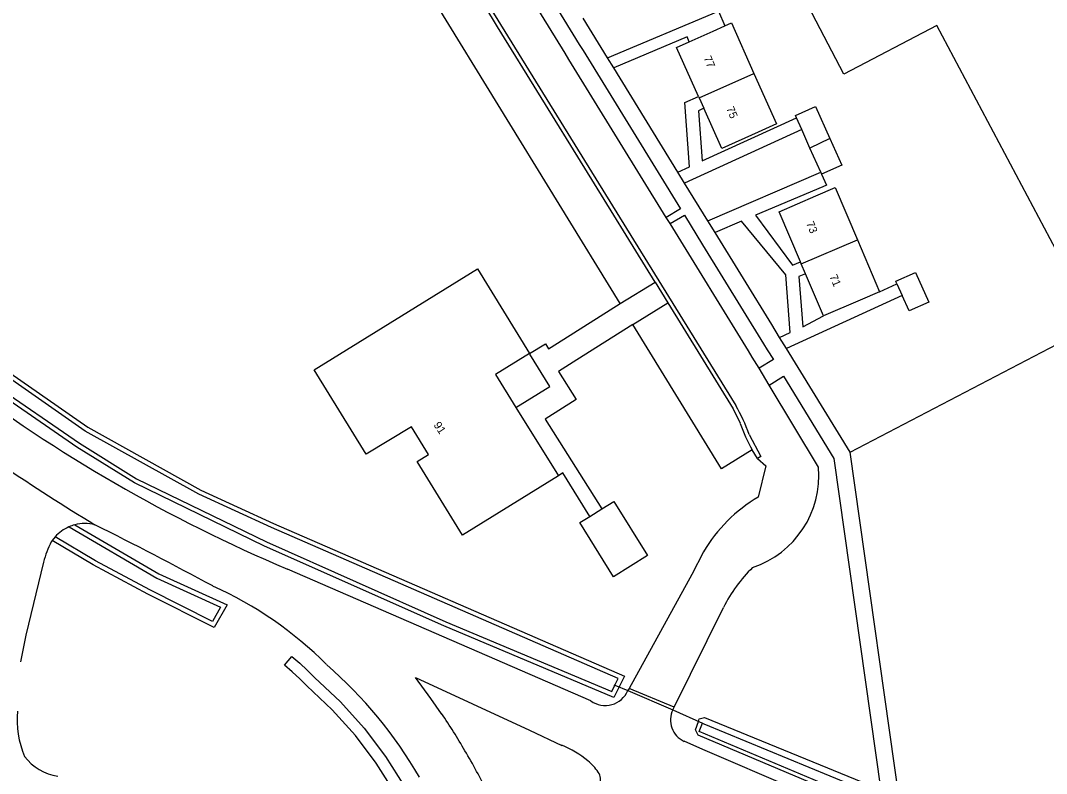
# Model space of a CAD drawing. Extents: x 158132 to 159658, y 385257 to 387209.
# Drawn here: x 158545 to 158673.1, y 386868.4 to 386962.3 of the extents above; entities that cross this region are included whole.
import ezdxf

# ---------------------------------------------------------------- set-up
doc = ezdxf.new("R2010")
doc.units = 0
for name, color, linetype in [('IMGEO_Duiker', 7, 'Continuous'), ('IMGEO_Gemengd_bos', 7, 'Continuous'), ('IMGEO_Groenvoorziening', 7, 'Continuous'), ('IMGEO_Pand', 7, 'Continuous'), ('IMGEO_Pand_nummerreeks', 7, 'Continuous'), ('IMGEO_Pand_overbouw', 7, 'Continuous'), ('IMGEO_Parkeervlak_open', 7, 'Continuous'), ('IMGEO_Rijbaan_lokaal_gesloten', 7, 'Continuous'), ('IMGEO_Rijbaan_lokaal_open', 7, 'Continuous'), ('IMGEO_Voetpad_gesloten', 7, 'Continuous'), ('IMGEO_Voetpad_open', 7, 'Continuous'), ('IMGEO_Waterloop', 7, 'Continuous')]:
    doc.layers.add(name, color=color, linetype=linetype)

msp = doc.modelspace()

# ---------------------------------------------------------------- linework, layer by layer
at = {"layer": 'IMGEO_Duiker'}
msp.add_lwpolyline([(158619.11, 386879.44), (158619.24, 386879.39), (158620.83, 386878.7), (158626.46, 386876.3), (158630.15, 386874.64), (158630.33, 386874.56)], dxfattribs=at)
at = {"layer": 'IMGEO_Gemengd_bos'}
msp.add_lwpolyline([(158648.61, 386908.46), (158679.26, 386924.45), (158659.44, 386961.72), (158647.81, 386955.65), (158601.87, 387043.7)], dxfattribs=at)
at = {"layer": 'IMGEO_Groenvoorziening'}
for points in [[(158541.3, 386919.97), (158553.38, 386911.58), (158567.53, 386903.71), (158576.57, 386899.58), (158620.42, 386880.49), (158619.77, 386879.16), (158619.11, 386877.83), (158597.88, 386886.78), (158575.48, 386896.74), (158559.21, 386904.65), (158552.04, 386909.09), (158541.19, 386916.52)], [(158551.76, 386899.4), (158562.26, 386893.26), (158570.79, 386889.39), (158569.19, 386886.59), (158560.89, 386890.75), (158554.07, 386894.41), (158548.96, 386897.43)], [(158651.05, 386866.89), (158651.9, 386866.34), (158651.69, 386865.11), (158651.3, 386864.28), (158650.59, 386864.28), (158629.61, 386873.15), (158629.28, 386873.81), (158629.65, 386874.86), (158629.77, 386875.18), (158630.42, 386875.36), (158651.05, 386866.89)]]:
    msp.add_lwpolyline(points, dxfattribs=at)
at = {"layer": 'IMGEO_Pand'}
for points in [[(158628.51, 386959.69), (158631.48, 386961.02), (158632.96, 386961.69)], [(158632.96, 386961.69), (158633.78, 386962.05), (158636.6, 386955.75)], [(158629.66, 386952.87), (158626.92, 386958.98), (158628.51, 386959.69)], [(158629.74, 386952.68), (158636.6, 386955.75)], [(158636.6, 386955.75), (158639.43, 386949.45), (158637.13, 386948.42), (158632.57, 386946.38), (158630.32, 386951.39)], [(158629.66, 386952.87), (158629.74, 386952.68)], [(158629.74, 386952.68), (158630.32, 386951.39)], [(158641.9, 386950.19), (158641.77, 386950.48), (158644.28, 386951.61), (158646.08, 386947.6)], [(158642.56, 386948.72), (158641.9, 386950.19)], [(158643.58, 386946.43), (158642.56, 386948.72)], [(158646.08, 386947.6), (158643.58, 386946.43)], [(158646.08, 386947.6), (158647.57, 386944.29), (158645.05, 386943.16)], [(158644.93, 386943.42), (158643.58, 386946.43)], [(158644.93, 386943.42), (158645.05, 386943.16)], [(158642.39, 386932.24), (158639.73, 386938.48), (158644.33, 386940.45), (158646.74, 386941.48), (158649.51, 386934.98)], [(158642.5, 386931.99), (158649.51, 386934.98)], [(158649.51, 386934.98), (158652.28, 386928.48)], [(158642.5, 386931.99), (158642.39, 386932.24)], [(158643.03, 386930.74), (158642.5, 386931.99)], [(158612.17, 386905.52), (158600.21, 386898.12), (158594.54, 386907.31), (158595.94, 386908.17), (158593.81, 386911.62), (158588.18, 386908.2), (158581.66, 386918.75), (158602.06, 386931.34), (158608.58, 386920.77)], [(158645.27, 386925.49), (158643.03, 386930.74)], [(158654.46, 386929.47), (158654.32, 386929.79), (158656.77, 386930.89), (158658.43, 386927.19), (158655.98, 386926.09), (158655.12, 386928.01)], [(158654.46, 386929.47), (158655.12, 386928.01)], [(158652.28, 386928.48), (158649.87, 386927.45), (158645.27, 386925.49)], [(158608.58, 386920.77), (158604.31, 386918.14), (158606.86, 386914.04), (158612.17, 386905.52)], [(158617.6, 386901.39), (158619.1, 386902.32), (158623.29, 386895.56), (158619.04, 386892.92), (158614.85, 386899.68), (158616.09, 386900.45)], [(158616.09, 386900.45), (158617.6, 386901.39)]]:
    msp.add_lwpolyline(points, dxfattribs=at)
at = {"layer": 'IMGEO_Pand_overbouw'}
msp.add_lwpolyline([(158608.62, 386920.71), (158608.58, 386920.77), (158604.31, 386918.14), (158606.86, 386914.04), (158611.12, 386916.66)], close=True, dxfattribs=at)
at = {"layer": 'IMGEO_Parkeervlak_open'}
for points in [[(158619.87, 386927), (158597.01, 386964.2)], [(158636.39, 386908.74), (158632.55, 386906.39), (158621.45, 386924.4)]]:
    msp.add_lwpolyline(points, dxfattribs=at)
at = {"layer": 'IMGEO_Rijbaan_lokaal_gesloten'}
for points in [[(158548.96, 386897.43), (158548.84, 386897.27)], [(158549.31, 386897.89), (158548.96, 386897.43)], [(158547.87, 386894.73), (158545.66, 386885.64), (158544.99, 386882.31)], [(158616.23, 386877.41), (158578.35, 386893.85)], [(158597.59, 386875.82), (158596.25, 386877.72), (158594.32, 386880.32), (158601.45, 386877.03), (158608.58, 386873.75)], [(158620.99, 386878.98), (158620.83, 386878.7)], [(158626.63, 386876.64), (158620.99, 386878.98)], [(158626.46, 386876.3), (158626.63, 386876.64)], [(158608.58, 386873.75), (158612.61, 386871.86)], [(158653.1, 386861.53), (158630.22, 386871.36), (158627.88, 386872.37)]]:
    msp.add_lwpolyline(points, dxfattribs=at)
for centre, radius, start, end in [((158654.05, 387072.79), 194.29, 232.8648, 247.0704), ((158685.5, 387116.71), 253.85, 235.797, 238.8745), ((158553.03, 386894.54), 5.02, 75.5928, 104.6347), ((158553.05, 386894.56), 5.01, 113.585, 138.3403), ((158553.02, 386894.56), 5, 104.6401, 113.2873), ((158290.06, 386372.24), 589.68, 61.7656, 63.37979), ((158558.82, 386892), 11.29, 152.1703, 165.9761), ((158549.31, 386848.03), 47.96, 44.9925, 65.7313), ((158546.29, 386839.62), 56.17, 30.2156, 48.8784), ((158618.02, 386879.89), 3.05, 234.0752, 337.0449), ((158556.65, 386875.12), 12.09, 175.1111, 202.5936), ((158536.61, 386834.47), 73.68, 29.8955, 34.1441), ((158629.12, 386875.04), 2.95, 154.6443, 244.9163), ((158608.51, 386861.33), 11.31, 49.4858, 68.7477), ((158550.73, 386874.54), 6.63, 217.748, 260.4791), ((158554.48, 386843.09), 53.91, 25.1163, 31.4145), ((158611.64, 386864.78), 6.65, 34.1317, 50.6535), ((158615.64, 386867.55), 1.79, 341.2257, 32.5098)]:
    msp.add_arc(centre, radius, start, end, dxfattribs=at)
at = {"layer": 'IMGEO_Rijbaan_lokaal_open'}
for points in [[(158580.35, 387001.58), (158581.34, 387000), (158585.64, 386993.16), (158585.72, 386993.03), (158634.35, 386914.28)], [(158625.65, 386937.74), (158613.49, 386957.48), (158613, 386958.27), (158600.65, 386978.31)], [(158624.24, 386929.68), (158615.46, 386943.91), (158604.58, 386961.57), (158603.95, 386962.59), (158601.32, 386966.86)], [(158626.11, 386936.99), (158625.65, 386937.74)], [(158637.23, 386918.93), (158636.39, 386920.31), (158635.9, 386921.1), (158626.11, 386936.99)], [(158624.24, 386929.68), (158625.84, 386927.1)], [(158625.84, 386927.1), (158633.99, 386913.88), (158634.88, 386912.07)], [(158638.49, 386916.84), (158637.23, 386918.93)], [(158644.67, 386906.58), (158638.49, 386916.84)], [(158636, 386910.68), (158637.46, 386907.91), (158637.04, 386907.66)], [(158637.04, 386907.66), (158636.39, 386908.74)], [(158637.04, 386907.66), (158638.07, 386906.76), (158637.14, 386902.85)], [(158630.3, 386896.03), (158628.83, 386893.2), (158620.99, 386878.98)], [(158626.63, 386876.64), (158632.8, 386889.08)]]:
    msp.add_lwpolyline(points, dxfattribs=at)
for centre, radius, start, end in [((158612.98, 386902.31), 24.49, 19.9902, 29.2734), ((158654.01, 386918.74), 20.27, 199.2354, 209.5693), ((158632.57, 386905.57), 12.14, 288.5275, 4.7665), ((158646.8, 386886.32), 19.15, 120.2949, 149.5374), ((158649.18, 386880.95), 18.29, 134.2193, 153.6111)]:
    msp.add_arc(centre, radius, start, end, dxfattribs=at)
at = {"layer": 'IMGEO_Voetpad_gesloten'}
for points in [[(158600.65, 386978.31), (158602.48, 386979.4), (158614.78, 386959.36), (158615.26, 386958.58), (158627.4, 386938.84), (158625.65, 386937.74)], [(158618.31, 386957.7), (158615.27, 386962.63)], [(158619.08, 386956.45), (158618.31, 386957.7)], [(158627.09, 386943.43), (158619.08, 386956.45)], [(158627.94, 386942.05), (158627.09, 386943.43)], [(158630.85, 386937.34), (158627.94, 386942.05)], [(158626.11, 386936.99), (158627.91, 386938.04), (158630.17, 386934.34), (158637.79, 386922), (158638.26, 386921.25), (158639.02, 386920.01), (158637.23, 386918.93)], [(158631.73, 386935.9), (158630.85, 386937.34)], [(158639.8, 386922.79), (158638.81, 386924.4), (158631.73, 386935.9)], [(158640.65, 386921.41), (158639.8, 386922.79)], [(158648.61, 386908.46), (158640.65, 386921.41)], [(158638.49, 386916.84), (158640.3, 386917.93), (158646.58, 386907.68), (158653.1, 386861.53)], [(158655.38, 386860.52), (158648.61, 386908.46)]]:
    msp.add_lwpolyline(points, dxfattribs=at)
at = {"layer": 'IMGEO_Voetpad_open'}
for points in [[(158618.31, 386957.7), (158632.15, 386963.51)], [(158632.15, 386963.51), (158632.96, 386961.69)], [(158628.51, 386959.69), (158628.24, 386960.3), (158619.08, 386956.45)], [(158627.09, 386943.43), (158628.56, 386944.1), (158627.97, 386952.1), (158629.66, 386952.87)], [(158630.32, 386951.39), (158629.67, 386951.09), (158630.14, 386944.82), (158641.9, 386950.19)], [(158642.56, 386948.72), (158627.94, 386942.05)], [(158630.85, 386937.34), (158644.93, 386943.42)], [(158645.05, 386943.16), (158645.66, 386941.8), (158645.19, 386941.6), (158636.77, 386938.03), (158641.41, 386931.79), (158642.39, 386932.24)], [(158639.8, 386922.79), (158641.1, 386923.39), (158640.57, 386930.58), (158635.02, 386937.29), (158631.73, 386935.9)], [(158643.03, 386930.74), (158642.21, 386930.37), (158642.68, 386924.1), (158645.27, 386925.49)], [(158619.87, 386927), (158624.24, 386929.68)], [(158652.28, 386928.48), (158654.46, 386929.47)], [(158655.12, 386928.01), (158640.65, 386921.41)], [(158608.58, 386920.77), (158610.54, 386921.98), (158610.94, 386921.35), (158612.85, 386922.56), (158619.87, 386927)], [(158621.45, 386924.4), (158625.84, 386927.1)], [(158621.45, 386924.4), (158614.47, 386919.99), (158612.17, 386918.54), (158614.39, 386915.04), (158610.51, 386912.59), (158617.6, 386901.39)], [(158616.09, 386900.45), (158612.74, 386905.87), (158612.17, 386905.52)]]:
    msp.add_lwpolyline(points, dxfattribs=at)
at = {"layer": 'IMGEO_Waterloop'}
for points in [[(158493.14, 386965.19), (158500, 386957.28), (158506.24, 386950.07), (158518.11, 386937.09), (158528.53, 386927.48), (158541.53, 386916.98), (158552.35, 386909.57), (158559.49, 386905.15), (158575.73, 386897.26), (158598.11, 386887.3), (158618.84, 386878.57), (158619.24, 386879.39), (158619.65, 386880.21), (158576.34, 386899.06), (158567.28, 386903.2), (158553.08, 386911.1), (158540.96, 386919.52), (158529.8, 386928.99), (158519.42, 386938.44), (158507.66, 386951.32), (158500, 386960.09), (158494.74, 386966.11)], [(158551.05, 386899.15), (158562, 386892.75), (158569.98, 386889.13), (158568.96, 386887.34), (158561.16, 386891.26), (158554.35, 386894.91), (158549.31, 386897.89)], [(158591.76, 386865.98), (158589.43, 386869.64), (158586.81, 386873.1), (158583.92, 386876.32), (158580.76, 386879.3), (158579.86, 386880.18), (158578.93, 386881.04), (158577.98, 386881.87), (158578.89, 386882.96), (158579.86, 386882.11), (158580.81, 386881.24), (158581.73, 386880.34), (158584.95, 386877.29), (158587.91, 386874), (158590.59, 386870.47), (158592.97, 386866.73)], [(158630.15, 386874.64), (158630.33, 386874.56), (158651.3, 386865.91), (158651.3, 386865.58), (158651.1, 386864.61), (158629.77, 386873.58), (158630.15, 386874.64)]]:
    msp.add_lwpolyline(points, dxfattribs=at)

# ---------------------------------------------------------------- texts
at = {"layer": 'IMGEO_Pand_nummerreeks'}
for s, rotation, p in [('77', 292.9754, (158630.28, 386957.68)), ('75', 292.9754, (158633.11, 386951.37)), ('73', 292.9754, (158643.09, 386937.03)), ('71', 292.9754, (158646.01, 386930.4)), ('91', 303.9475, (158596.53, 386911.85))]:
    msp.add_text(s, height=1, rotation=rotation, dxfattribs=at).set_placement(p)

doc.saveas('drawing.dxf')
